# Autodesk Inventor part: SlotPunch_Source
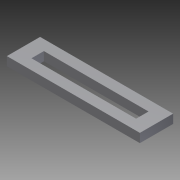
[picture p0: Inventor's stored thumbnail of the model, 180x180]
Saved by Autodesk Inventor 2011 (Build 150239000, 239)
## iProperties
Created: 2007-02
Part Number: SlotPunch_Source
Material: Default
Document SubType Name: Sheet Metal
Designer: Autodesk, Inc.
Mass: 0.03973 g
Surface Area: 1.4336 cm^2
Volume: 0.03973 cm^3
Density: 1 g/cm^3
Sheet Metal Rule: 1 mm
Author: Autodesk, Inc.
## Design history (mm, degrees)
node "Face1"
  sketch "Sketch1"
    geometry: L1 (-7.5, 1.875)-(7.5, 1.875); L2 (7.5, 1.875)-(7.5, -1.875); L3 (7.5, -1.875)-(-7.5, -1.875); L4 (-7.5, -1.875)-(-7.5, 1.875); L5 (-7.5, 1.875)-(7.5, -1.875); 2 further points
    constraints: 10 end point, 2 parallel, 1 coincident, 1 horizontal, 1 midpoint, 1 perpendicular
    dimensions: "d0" = 15 distance of L2.end L3.end; "d1" = 3.75 distance of L3.end L1.start (= 0.25 x d0)
sketch "Sketch2"
  geometry: L1 (-5.9, 0.7)-(5.9, 0.7); L2 (5.9, 0.7)-(5.9, -0.7); L3 (5.9, -0.7)-(-5.9, -0.7); L4 (-5.9, -0.7)-(-5.9, 0.7); L5 (-5.9, 0.7)-(5.9, -0.7); 3 further points
  constraints: 10 end point, 2 coincident, 2 parallel, 1 horizontal, 1 midpoint, 1 perpendicular
  dimensions: "d3" = 11.8 distance of L1.start L1.end; "d4" = 1.4 distance of L1.end L2.end
cut "Cut1" sketch "Sketch2" dims "d5" = 1 (= Thickness), "d6" = 0
body "Solid1"
face "Plate1" dims "Thickness" = 1
other parameters: "BendRadius" = 0.5, "BendReliefWidth" = 1 (= Thickness), "BendReliefDepth" = 0.5 (= 0.5 x Thickness), "CornerReliefSize" = 4 (= 4 x Thickness), "SeamGap" = 0.01, "MinimumRemnant" = 2 (= 2 x Thickness), "TransitionRadius" = 0.5 (= BendRadius), "JacobiRadiusSize" = 1 (= Thickness), "d2" = 0.5 (= BendRadius), "GapSize" = 1 (= Thickness)
